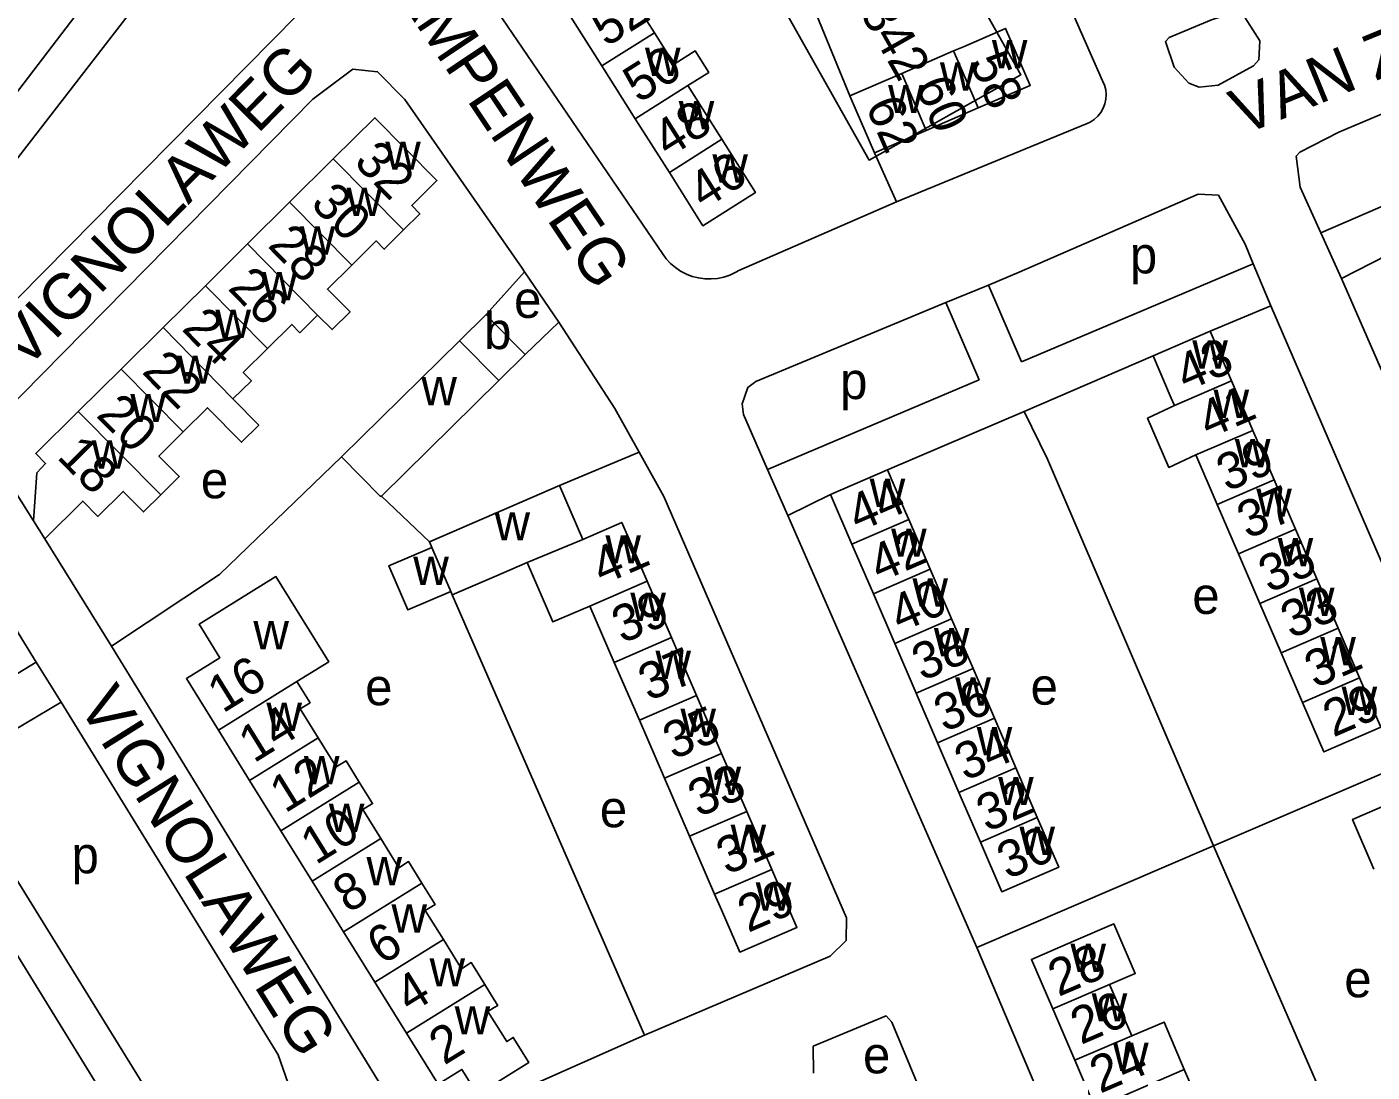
# Model space of a CAD drawing. Extents: x 158848 to 160613, y 385889 to 387762.
# Drawn here: x 159449.2 to 159595.5, y 386296 to 386409.7 of the extents above; entities that cross this region are included whole.
import ezdxf

# ---------------------------------------------------------------- set-up
doc = ezdxf.new("R2010")
doc.units = 0
for name, color, linetype in [('BLT_Basislijn', 7, 'Continuous'), ('BLT_Bebouwing', 7, 'Continuous'), ('BLT_Centroide', 7, 'Continuous'), ('BLT_Huisnummer', 7, 'Continuous'), ('BLT_Huisnummer_ tussenligend', 7, 'Continuous'), ('BLT_Huisnummer_zonder_bebouwing', 7, 'Continuous'), ('BLT_Onderverdeling_panden', 7, 'Continuous'), ('BLT_Plantopo', 7, 'Continuous'), ('BLT_Straatnaam', 7, 'Continuous')]:
    doc.layers.add(name, color=color, linetype=linetype)

msp = doc.modelspace()

# ---------------------------------------------------------------- linework, layer by layer
at = {"layer": 'BLT_Basislijn'}
for p, q in [((159491.08, 386424.94), (159518.29, 386385)), ((159559.12, 386419.76), (159566.17, 386403.78)), ((159533.91, 386413.81), (159538.67, 386402.16)), ((159564.48, 386399.14), (159543.76, 386390.64)), ((159589.89, 386387.24), (159613.57, 386397.5)), ((159543.76, 386390.64), (159541.35, 386395.96)), ((159526.6, 386383.17), (159543.76, 386390.64)), ((159589.89, 386387.24), (159592.13, 386382.31)), ((159597.11, 386384.84), (159592.13, 386382.31)), ((159503.3, 386383.02), (159499.1, 386378.36)), ((159503.3, 386383.02), (159507.02, 386377.53)), ((159557.33, 386373.23), (159582.54, 386383.9)), ((159582.54, 386383.9), (159584.47, 386379.32)), ((159549.13, 386379.67), (159553.75, 386381.58)), ((159553.75, 386381.58), (159557.33, 386373.23)), ((159592.13, 386382.31), (159612.31, 386336.07)), ((159549.13, 386379.67), (159552.73, 386371.28)), ((159584.47, 386379.32), (159577.87, 386376.55)), ((159604.87, 386332.01), (159584.47, 386379.32)), ((159507.02, 386377.53), (159503.35, 386374.04)), ((159571.65, 386373.87), (159557.62, 386367.82)), ((159529.7, 386361.52), (159552.73, 386371.28)), ((159557.62, 386367.82), (159542.76, 386361.47)), ((159507.1, 386359.77), (159515.75, 386363.42)), ((159529.7, 386361.52), (159531.94, 386356.52)), ((159487.72, 386358.63), (159487.59, 386358.64)), ((159492.94, 386353.64), (159487.72, 386358.63)), ((159531.94, 386356.52), (159536.57, 386358.8)), ((159531.94, 386356.52), (159552.48, 386309.54)), ((159516.34, 386300.01), (159495.43, 386347.89)), ((159450.18, 386340.58), (159452.9, 386336.22)), ((159578.22, 386320.6), (159604.87, 386332.01)), ((159552.48, 386309.54), (159578.22, 386320.6)), ((159599.85, 386270.89), (159578.22, 386320.6)), ((159573.77, 386259.36), (159552.48, 386309.54))]:
    msp.add_line(p, q, dxfattribs=at)
for points in [[(159473, 386432.36), (159462.11, 386420.94), (159440.16, 386392.21), (159414.81, 386370.75), (159413.46, 386368.41), (159413.43, 386365.42), (159415.73, 386361.26), (159495.3, 386232.05)], [(159450.18, 386340.58), (159439.6, 386334.13), (159437.93, 386333.69), (159418.04, 386365.52), (159418.17, 386367.3), (159419.09, 386369.02), (159444.29, 386390.46), (159467.36, 386420.26), (159475.74, 386428.18)], [(159475.74, 386428.18), (159481.84, 386418.87), (159481.99, 386418.14), (159481.36, 386413.78), (159439.89, 386371.77), (159438.58, 386370.38), (159436.98, 386366.85), (159437.23, 386361.6), (159450.18, 386340.58)], [(159577.99, 386410.41), (159573.39, 386408.49), (159572.99, 386408.05), (159573.95, 386405.27), (159575.54, 386403.54), (159576.65, 386403.09), (159578.72, 386403.31), (159582.57, 386405.43), (159583.17, 386406.08), (159583.27, 386408.15), (159581.15, 386411.45), (159577.99, 386410.41)], [(159503.3, 386383.02), (159503.03, 386383.43), (159490.27, 386401.77), (159487.31, 386404.77), (159484.6, 386405.06), (159480.25, 386401.81), (159446.33, 386367.32), (159445.53, 386365.96), (159445.28, 386364.02), (159446.02, 386362.06), (159449.89, 386355.94)], [(159589.89, 386387.24), (159587.65, 386392.22), (159587.21, 386395.58), (159587.6, 386396.03), (159591.86, 386398.22), (159609.86, 386405.82)], [(159566.17, 386403.78), (159566.37, 386403.32), (159566.5, 386402.82), (159566.55, 386402.3), (159566.52, 386401.79), (159566.41, 386401.28), (159566.22, 386400.8), (159565.96, 386400.35), (159565.64, 386399.94), (159565.26, 386399.59), (159564.82, 386399.3), (159564.48, 386399.14)], [(159553.75, 386381.58), (159557.1, 386382.97), (159576.55, 386391.48), (159578.76, 386391.37), (159581.66, 386386.01), (159582.54, 386383.9)], [(159518.29, 386385), (159518.7, 386384.44), (159519.17, 386383.93), (159519.7, 386383.48), (159520.27, 386383.09), (159520.89, 386382.77), (159521.54, 386382.52), (159522.21, 386382.35), (159522.9, 386382.25), (159523.6, 386382.24), (159524.29, 386382.3), (159524.97, 386382.45), (159525.63, 386382.67), (159526.26, 386382.97), (159526.6, 386383.17)], [(159529.7, 386361.52), (159527.11, 386367.52), (159526.95, 386368.67), (159527.56, 386370.45), (159528.45, 386371.08), (159549.13, 386379.67)], [(159507.02, 386377.53), (159513.13, 386368.16), (159515.75, 386363.42)], [(159557.62, 386367.82), (159560.18, 386362.63), (159578.22, 386320.6)], [(159458.38, 386342.3), (159470.1, 386350.1), (159483.4, 386362.89)], [(159515.75, 386363.42), (159518.43, 386358.58), (159538.31, 386312.76), (159538.26, 386310.3), (159536.54, 386308.6), (159516.34, 386300.01)], [(159451.1, 386353.99), (159458.38, 386342.3)], [(159458.38, 386342.3), (159488.36, 386293.44), (159491.54, 386290.75), (159495.68, 386290.84), (159516.34, 386300.01)], [(159482.97, 386270.09), (159479.35, 386268.12), (159478.69, 386267.99), (159477.99, 386268.46), (159440.73, 386328.77), (159440.95, 386329.15), (159452.9, 386336.22)], [(159482.97, 386270.09), (159479.29, 386276.39), (159477.85, 386280.53), (159478.1, 386293.32), (159476.49, 386297.87), (159452.9, 386336.22)], [(159546.35, 386293.97), (159546.18, 386294.37), (159543.24, 386301.41), (159542.61, 386302.11), (159534.7, 386298.8), (159534.73, 386295.87)]]:
    msp.add_lwpolyline(points, dxfattribs=at)
at = {"layer": 'BLT_Bebouwing'}
for p, q in [((159513.75, 386414.8), (159517.42, 386409.01)), ((159511.71, 386405.4), (159508.04, 386411.19)), ((159549.96, 386407.04), (159544.31, 386404.6)), ((159515.34, 386399.66), (159511.71, 386405.4)), ((159544.31, 386404.6), (159538.67, 386402.16)), ((159521.05, 386403.27), (159524.74, 386397.43)), ((159546.99, 386398.4), (159552.64, 386400.84)), ((159519.04, 386393.82), (159515.34, 386399.66)), ((159541.35, 386395.96), (159546.99, 386398.4)), ((159482.49, 386395.29), (159477.74, 386390.59)), ((159477.74, 386390.59), (159473.16, 386386.05)), ((159473.16, 386386.05), (159468.58, 386381.51)), ((159468.58, 386381.51), (159463.99, 386376.98)), ((159499.1, 386378.36), (159496.22, 386375.52)), ((159463.99, 386376.98), (159459.41, 386372.44)), ((159496.22, 386375.52), (159483.4, 386362.89)), ((159577.87, 386376.55), (159571.65, 386373.87)), ((159580.18, 386371.16), (159577.87, 386376.55)), ((159503.35, 386374.04), (159500.48, 386371.21)), ((159459.41, 386372.44), (159454.76, 386367.84)), ((159487.72, 386358.63), (159500.48, 386371.21)), ((159582.51, 386365.78), (159580.18, 386371.16)), ((159584.82, 386360.4), (159582.51, 386365.78)), ((159483.4, 386362.89), (159487.59, 386358.64)), ((159576.29, 386363.1), (159578.61, 386357.72)), ((159536.57, 386358.8), (159542.76, 386361.47)), ((159509.62, 386353.92), (159507.1, 386359.77)), ((159587.14, 386355.02), (159584.82, 386360.4)), ((159487.59, 386358.64), (159487.66, 386358.57)), ((159487.66, 386358.57), (159487.72, 386358.63)), ((159538.9, 386353.4), (159536.57, 386358.8)), ((159578.61, 386357.72), (159580.93, 386352.34)), ((159449.89, 386355.94), (159451.1, 386353.99)), ((159545.09, 386356.07), (159547.42, 386350.67)), ((159589.46, 386349.64), (159587.14, 386355.02)), ((159492.94, 386353.64), (159493.2, 386353.03)), ((159541.23, 386348), (159538.9, 386353.4)), ((159580.93, 386352.34), (159583.25, 386346.96)), ((159547.42, 386350.67), (159549.74, 386345.27)), ((159516.63, 386349.37), (159519.28, 386343.25)), ((159591.78, 386344.26), (159589.46, 386349.64)), ((159495.26, 386348.27), (159495.43, 386347.89)), ((159543.56, 386342.6), (159541.23, 386348)), ((159513.05, 386340.55), (159510.39, 386346.67)), ((159583.25, 386346.96), (159585.57, 386341.58)), ((159549.74, 386345.27), (159552.07, 386339.87)), ((159519.28, 386343.25), (159522.01, 386336.95)), ((159594.1, 386338.88), (159591.78, 386344.26)), ((159545.88, 386337.2), (159543.56, 386342.6)), ((159515.78, 386334.25), (159513.05, 386340.55)), ((159585.57, 386341.58), (159587.89, 386336.2)), ((159552.07, 386339.87), (159554.4, 386334.47)), ((159522.01, 386336.95), (159524.73, 386330.65)), ((159548.21, 386331.8), (159545.88, 386337.2)), ((159554.4, 386334.47), (159556.73, 386329.07)), ((159473.39, 386327.71), (159469.99, 386333.19)), ((159518.51, 386327.95), (159515.78, 386334.25)), ((159550.54, 386326.4), (159548.21, 386331.8)), ((159524.73, 386330.65), (159527.46, 386324.35)), ((159556.73, 386329.07), (159559.06, 386323.67)), ((159476.79, 386322.24), (159473.39, 386327.71)), ((159521.24, 386321.65), (159518.51, 386327.95)), ((159552.87, 386321), (159550.54, 386326.4)), ((159527.46, 386324.35), (159530.18, 386318.04)), ((159480.19, 386316.75), (159476.79, 386322.24)), ((159523.97, 386315.35), (159521.24, 386321.65)), ((159483.6, 386311.26), (159480.19, 386316.75)), ((159487, 386305.77), (159483.6, 386311.26)), ((159490.44, 386300.23), (159487, 386305.77)), ((159569.33, 386299.95), (159566.93, 386305.53)), ((159563.14, 386297.28), (159560.74, 386302.86)), ((159565.37, 386292.11), (159563.14, 386297.28))]:
    msp.add_line(p, q, dxfattribs=at)
for points in [[(159517.42, 386409.01), (159519.57, 386405.61), (159521.84, 386407.05), (159523.32, 386404.71), (159521.05, 386403.27)], [(159552.64, 386400.84), (159558.29, 386403.28), (159555.61, 386409.48), (159551.02, 386407.5), (159549.96, 386407.04)], [(159538.67, 386402.16), (159539.37, 386400.55), (159541.35, 386395.96)], [(159490.14, 386387.57), (159491.92, 386389.32), (159491.03, 386390.22), (159493.77, 386392.94), (159487.01, 386399.77), (159482.49, 386395.29)], [(159524.74, 386397.43), (159528.4, 386391.64), (159522.7, 386388.03), (159519.04, 386393.82)], [(159490.14, 386387.57), (159488.36, 386385.81), (159488.03, 386385.47), (159487.14, 386386.37), (159484.5, 386383.76)], [(159484.5, 386383.76), (159481.86, 386381.14), (159484.31, 386378.67), (159482.36, 386376.74), (159480.79, 386378.31)], [(159480.79, 386378.31), (159478.86, 386376.4), (159477.98, 386377.3), (159475.34, 386374.69)], [(159503.35, 386374.04), (159500, 386377.44), (159499.1, 386378.36)], [(159475.34, 386374.69), (159472.7, 386372.07), (159473.59, 386371.18), (159471.58, 386369.19)], [(159571.65, 386373.87), (159573.63, 386369.28), (159573.97, 386368.49)], [(159471.58, 386369.19), (159474.39, 386366.34), (159472.52, 386364.49), (159468.82, 386368.23), (159466.17, 386365.61)], [(159573.97, 386368.49), (159571.05, 386367.1), (159573.35, 386361.75), (159576.29, 386363.1)], [(159454.76, 386367.84), (159450.13, 386363.25), (159451.2, 386362.17), (159450.23, 386361.16), (159449.89, 386355.94)], [(159463.73, 386358.78), (159465.74, 386360.77), (159463.53, 386362.99), (159466.17, 386365.61)], [(159542.76, 386361.47), (159544.74, 386356.88), (159545.09, 386356.07)], [(159507.1, 386359.77), (159500, 386356.7), (159492.94, 386353.64)], [(159451.1, 386353.99), (159455.24, 386358.09), (159456.89, 386356.42), (159459.64, 386359.14), (159461.84, 386356.91), (159463.73, 386358.78)], [(159509.62, 386353.92), (159513.87, 386355.76), (159516.63, 386349.37)], [(159493.2, 386353.03), (159488.53, 386351.03), (159490.59, 386346.26), (159495.26, 386348.27)], [(159495.43, 386347.89), (159500, 386349.86), (159503.58, 386351.41)], [(159510.39, 386346.67), (159506.38, 386344.94), (159503.58, 386351.41)], [(159469.99, 386333.19), (159466.52, 386338.79), (159470.16, 386341.05), (159467.9, 386344.7), (159476.25, 386349.88), (159481.99, 386340.62), (159478.53, 386338.48)], [(159587.89, 386336.2), (159590.21, 386330.81), (159591.83, 386331.51), (159596.42, 386333.49), (159594.1, 386338.88)], [(159480.85, 386332.34), (159478.9, 386335.49), (159479.97, 386336.15), (159478.53, 386338.48)], [(159485.32, 386327.53), (159483.88, 386329.85), (159482.81, 386329.18), (159480.85, 386332.34)], [(159487.65, 386321.38), (159485.69, 386324.54), (159486.76, 386325.2), (159485.32, 386327.53)], [(159595.67, 386318.08), (159593.35, 386323.47), (159594.95, 386324.16), (159599.54, 386326.14), (159601.86, 386320.75)], [(159559.06, 386323.67), (159561.39, 386318.27), (159559.79, 386317.58), (159555.2, 386315.6), (159552.87, 386321)], [(159492.13, 386316.55), (159490.68, 386318.88), (159489.61, 386318.21), (159487.65, 386321.38)], [(159530.18, 386318.04), (159532.91, 386311.73), (159526.71, 386309.05), (159524.72, 386313.64), (159523.97, 386315.35)], [(159494.46, 386310.4), (159492.5, 386313.56), (159493.57, 386314.22), (159492.13, 386316.55)], [(159560.74, 386302.86), (159558.42, 386308.24), (159563.01, 386310.22), (159567.4, 386312.11), (159569.72, 386306.72), (159566.93, 386305.53)], [(159498.97, 386305.52), (159497.74, 386307.5), (159497.49, 386307.91), (159496.42, 386307.24), (159494.46, 386310.4)], [(159498.97, 386305.52), (159500, 386303.86), (159500.38, 386303.25), (159500, 386303.02), (159499.31, 386302.59), (159500, 386301.48), (159501.35, 386299.31), (159502.07, 386299.77), (159503.77, 386297.04), (159498.18, 386293.57), (159496.48, 386296.29), (159493.88, 386294.68), (159490.44, 386300.23)], [(159575.03, 386296.28), (159572.86, 386301.43), (159569.33, 386299.95)], [(159573.88, 386289.41), (159577.38, 386290.85), (159575.03, 386296.28)]]:
    msp.add_lwpolyline(points, dxfattribs=at)
at = {"layer": 'BLT_Onderverdeling_panden'}
for p, q in [((159511.71, 386405.4), (159517.42, 386409.01)), ((159552.64, 386400.84), (159549.96, 386407.04)), ((159546.99, 386398.4), (159544.31, 386404.6)), ((159515.34, 386399.66), (159521.05, 386403.27)), ((159519.04, 386393.82), (159524.74, 386397.43)), ((159490.14, 386387.57), (159482.49, 386395.29)), ((159484.5, 386383.76), (159477.74, 386390.59)), ((159480.79, 386378.31), (159473.16, 386386.05)), ((159475.34, 386374.69), (159468.58, 386381.51)), ((159471.58, 386369.19), (159463.99, 386376.98)), ((159500.48, 386371.21), (159496.22, 386375.52)), ((159466.17, 386365.61), (159459.41, 386372.44)), ((159573.97, 386368.49), (159580.18, 386371.16)), ((159463.73, 386358.78), (159454.76, 386367.84)), ((159576.29, 386363.1), (159582.51, 386365.78)), ((159578.61, 386357.72), (159584.82, 386360.4)), ((159538.9, 386353.4), (159545.09, 386356.07)), ((159580.93, 386352.34), (159587.14, 386355.02)), ((159503.58, 386351.41), (159509.62, 386353.92)), ((159495.26, 386348.27), (159493.2, 386353.03)), ((159541.23, 386348), (159547.42, 386350.67)), ((159510.39, 386346.67), (159516.63, 386349.37)), ((159583.25, 386346.96), (159589.46, 386349.64)), ((159543.56, 386342.6), (159549.74, 386345.27)), ((159513.05, 386340.55), (159519.28, 386343.25)), ((159585.57, 386341.58), (159591.78, 386344.26)), ((159545.88, 386337.2), (159552.07, 386339.87)), ((159587.89, 386336.2), (159594.1, 386338.88)), ((159478.53, 386338.48), (159469.99, 386333.19)), ((159515.78, 386334.25), (159522.01, 386336.95)), ((159548.21, 386331.8), (159554.4, 386334.47)), ((159480.85, 386332.34), (159473.39, 386327.71)), ((159518.51, 386327.95), (159524.73, 386330.65)), ((159550.54, 386326.4), (159556.73, 386329.07)), ((159485.32, 386327.53), (159476.79, 386322.24)), ((159521.24, 386321.65), (159527.46, 386324.35)), ((159552.87, 386321), (159559.06, 386323.67)), ((159487.65, 386321.38), (159480.19, 386316.75)), ((159523.97, 386315.35), (159530.18, 386318.04)), ((159492.13, 386316.55), (159483.6, 386311.26)), ((159494.46, 386310.4), (159487, 386305.77)), ((159498.97, 386305.52), (159490.44, 386300.23)), ((159560.74, 386302.86), (159566.93, 386305.53)), ((159563.14, 386297.28), (159569.33, 386299.95)), ((159565.37, 386292.11), (159575.03, 386296.28))]:
    msp.add_line(p, q, dxfattribs=at)
at = {"layer": 'BLT_Plantopo'}
msp.add_lwpolyline([(159515.35, 386430.93), (159535.89, 386442.48), (159557.28, 386404.45), (159540.77, 386395.17), (159524.5, 386424.1), (159520.46, 386421.83)], close=True, dxfattribs=at)

# ---------------------------------------------------------------- texts
at = {"layer": 'BLT_Centroide'}
for s, p in [('w', (159554.12, 386405.16)), ('w', (159516.39, 386404.31)), ('w', (159548.47, 386402.72)), ('w', (159542.83, 386400.28)), ('w', (159520.06, 386398.52)), ('w', (159488.14, 386394.11)), ('w', (159523.72, 386392.73)), ('w', (159483.94, 386389.08)), ('w', (159478.83, 386384.89)), ('p', (159569.13, 386382.85)), ('w', (159474.69, 386379.92)), ('e', (159502.15, 386378.01)), ('w', (159469.67, 386375.83)), ('b', (159498.89, 386374.62)), ('w', (159575.92, 386372.5)), ('w', (159465.53, 386370.84)), ('w', (159492.07, 386368.5)), ('p', (159537.61, 386369.18)), ('w', (159460.41, 386366.67)), ('w', (159578.23, 386367.12)), ('w', (159456.22, 386361.62)), ('w', (159580.55, 386361.75)), ('e', (159468.09, 386358.39)), ('w', (159540.83, 386357.44)), ('w', (159582.88, 386356.38)), ('w', (159500.03, 386353.81)), ('w', (159543.16, 386352.03)), ('w', (159512.09, 386351.31)), ('w', (159585.2, 386351)), ('w', (159491.19, 386348.97)), ('w', (159545.48, 386346.62)), ('e', (159575.92, 386345.82)), ('w', (159514.8, 386345.05)), ('w', (159587.52, 386345.59)), ('w', (159473.8, 386341.97)), ('w', (159547.81, 386341.22)), ('w', (159589.84, 386340.22)), ('w', (159517.53, 386338.75)), ('e', (159485.95, 386335.89)), ('w', (159550.14, 386335.84)), ('e', (159558.33, 386335.95)), ('w', (159592.16, 386334.84)), ('w', (159475.22, 386333.09)), ('w', (159520.25, 386332.45)), ('w', (159552.47, 386330.44)), ('w', (159479.3, 386327.28)), ('w', (159522.98, 386326.14)), ('w', (159554.8, 386325.03)), ('e', (159511.48, 386322.62)), ('w', (159482.01, 386322.12)), ('w', (159525.7, 386319.84)), ('w', (159557.12, 386319.62)), ('p', (159454.02, 386317.61)), ('w', (159486.1, 386316.31)), ('w', (159528.44, 386313.55)), ('w', (159488.82, 386311.16)), ('w', (159562.67, 386306.88)), ('w', (159492.96, 386305.31)), ('e', (159592.45, 386304.13)), ('w', (159564.98, 386301.5)), ('w', (159495.69, 386300.09)), ('w', (159567.3, 386296.12)), ('e', (159540.1, 386295.86))]:
    msp.add_text(s, height=4, dxfattribs=at).set_placement(p)
at = {"layer": 'BLT_Huisnummer'}
for s, rotation, p in [('50', 32.3293, (159515.7, 386401.29)), ('58', 293.388, (159551.65, 386405.84)), ('62', 293.3505, (159540.34, 386401.09)), ('32', 314.7134, (159484.6, 386394.84)), ('46', 32.3293, (159522.78, 386389.73)), ('26', 314.7134, (159470.91, 386381.15)), ('43', 23.3085, (159575.23, 386369.97)), ('22', 314.7134, (159461.57, 386372.07)), ('18', 314.7134, (159452.32, 386362.8)), ('44', 23.325, (159539.55, 386354.68)), ('37', 23.3085, (159581.92, 386353.92)), ('41', 23.3789, (159511.73, 386348.92)), ('33', 23.3085, (159586.66, 386343.08)), ('38', 23.325, (159546.55, 386338.47)), ('37', 23.3789, (159516.8, 386336.29)), ('16', 31.802, (159470.47, 386334.96)), ('29', 23.3085, (159591.25, 386332.37)), ('34', 23.325, (159551.2, 386327.62)), ('33', 23.3789, (159522.21, 386323.66)), ('10', 31.802, (159480.59, 386318.47)), ('30', 23.325, (159555.81, 386316.91)), ('29', 23.3789, (159527.6, 386311.12)), ('6', 31.802, (159487.79, 386307.58)), ('28', 23.325, (159561.36, 386304.15)), ('2', 31.802, (159494.55, 386296.69))]:
    msp.add_text(s, height=4, rotation=rotation, dxfattribs=at).set_placement(p)
at = {"layer": 'BLT_Huisnummer_ tussenligend'}
for s, rotation, p in [('52', 32.3293, (159512.18, 386407.4)), ('60', 293.388, (159545.71, 386403.28)), ('48', 32.3293, (159518.93, 386395.35)), ('30', 314.7134, (159479.89, 386390.3)), ('28', 314.7134, (159475.24, 386385.8)), ('24', 314.7134, (159465.89, 386376.74)), ('20', 314.7134, (159456.6, 386367.35)), ('41', 23.3085, (159577.69, 386364.87)), ('39', 23.3085, (159579.68, 386359.06)), ('42', 23.325, (159541.9, 386349.23)), ('35', 23.3085, (159584.26, 386348.06)), ('40', 23.325, (159544.13, 386343.76)), ('39', 23.3789, (159513.92, 386342.55)), ('31', 23.3085, (159589.26, 386337.69)), ('36', 23.325, (159548.95, 386332.92)), ('35', 23.3789, (159519.48, 386329.92)), ('14', 31.802, (159473.85, 386329.54)), ('12', 31.802, (159477.24, 386324.09)), ('32', 23.325, (159553.57, 386322.05)), ('31', 23.3789, (159525.29, 386317.4)), ('8', 31.802, (159484.1, 386313.2)), ('4', 31.802, (159490.85, 386302.3)), ('26', 23.325, (159563.8, 386298.93)), ('24', 23.325, (159565.89, 386293.63))]:
    msp.add_text(s, height=4, rotation=rotation, dxfattribs=at).set_placement(p)
at = {"layer": 'BLT_Huisnummer_zonder_bebouwing'}
msp.add_text('240 t/m 342', height=4, rotation=299.5984, dxfattribs=at).set_placement((159530.16, 386428.06))
at = {"layer": 'BLT_Straatnaam'}
for s, rotation, p in [('JACOB VAN CAMPENWEG', 303.8166, (159464.07, 386450.81)), ('VAN ZINNICQSTRAAT', 22.2583, (159581.41, 386397.84)), ('VIGNOLAWEG', 45.472, (159448.99, 386372.25)), ('VIGNOLAWEG', 302.0867, (159454.65, 386335.93))]:
    msp.add_text(s, height=5, rotation=rotation, dxfattribs=at).set_placement(p)

doc.saveas('drawing.dxf')
